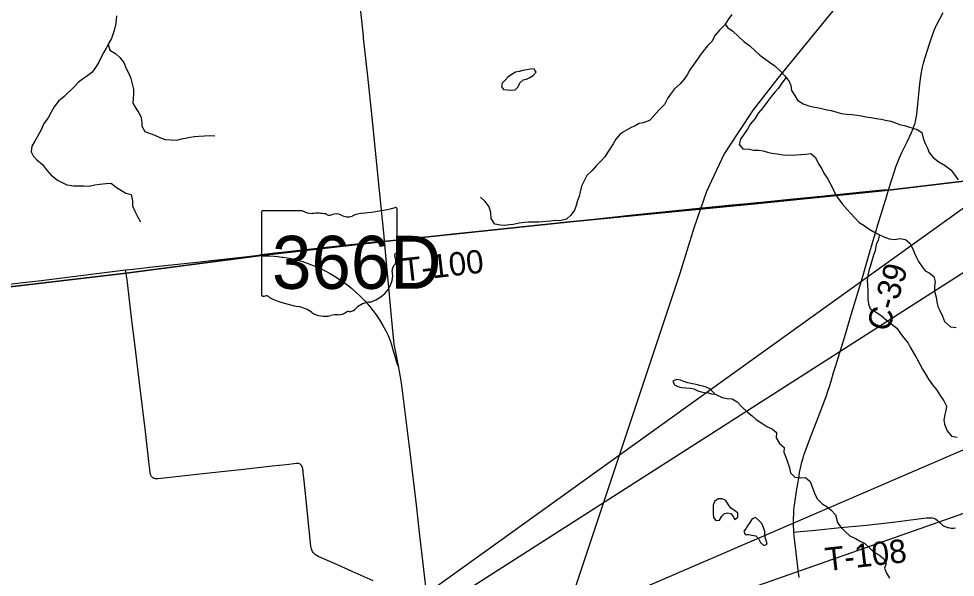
# Model space of a CAD drawing. Extents: x 0 to 34, y -5.4 to 22.
# Drawn here: x 5.117 to 7.394, y 18.075 to 19.432 of the extents above; entities that cross this region are included whole.
import ezdxf

# ---------------------------------------------------------------- set-up
doc = ezdxf.new("R2010")
doc.units = 0
for name, color, linetype in [('GM_X_County_Road', 7, 'Continuous'), ('GM_X_County_Road_Text', 7, 'Continuous'), ('GM_X_Minor_Lake', 7, 'Continuous'), ('GM_X_Minor_River', 7, 'Continuous'), ('GM_X_Rail_Line', 7, 'Continuous'), ('GM_X_State_Location', 7, 'Continuous'), ('GM_X_State_Route', 7, 'Continuous'), ('GM_X_State_Shield', 7, 'Continuous'), ('GM_X_Township_Road', 7, 'Continuous'), ('GM_X_Township_Road_Text', 7, 'Continuous'), ('SH_Data', 7, 'Continuous')]:
    doc.layers.add(name, color=color, linetype=linetype)

msp = doc.modelspace()

# ---------------------------------------------------------------- linework, layer by layer
at = {"layer": 'GM_X_County_Road'}
for points in [[(7.231, 19.0161), (7.2456, 19.0619), (7.249, 19.0719), (7.2529, 19.0817), (7.2574, 19.092), (7.264, 19.1068), (7.2768, 19.1331), (7.2875, 19.1555), (7.2915, 19.1651), (7.294, 19.1721), (7.296, 19.1785), (7.2972, 19.1834), (7.2986, 19.191), (7.2998, 19.1992), (7.3076, 19.274), (7.3107, 19.2969), (7.3124, 19.3059), (7.3142, 19.3146), (7.3165, 19.3238), (7.3179, 19.3294), (7.3196, 19.3351), (7.3315, 19.3731), (7.3408, 19.3995), (7.3434, 19.4059), (7.3457, 19.4111), (7.3483, 19.4166), (7.3639, 19.4471)], [(7.0144, 18.0746), (7.012, 18.0925), (7.0077, 18.1276), (7.0037, 18.1622), (7.0028, 18.1691), (7.0022, 18.175), (7.0014, 18.1844), (7.0008, 18.1919), (7.0005, 18.1991), (7.0002, 18.2066), (7.0002, 18.214), (7.0005, 18.2204), (7.0007, 18.2261), (7.0008, 18.2314), (7.0013, 18.2388), (7.0018, 18.2449), (7.0026, 18.2505), (7.0076, 18.2842), (7.0092, 18.2937), (7.0105, 18.302), (7.0121, 18.3118), (7.0137, 18.3204), (7.0152, 18.3294), (7.0174, 18.3399), (7.019, 18.3474), (7.0206, 18.3544), (7.0219, 18.3593), (7.0234, 18.3652), (7.0253, 18.3712), (7.0276, 18.3781), (7.03, 18.3848), (7.0332, 18.3932), (7.0449, 18.4233), (7.0605, 18.4633), (7.0775, 18.508), (7.0806, 18.5168), (7.0841, 18.5268), (7.0885, 18.5411), (7.0909, 18.5488), (7.0986, 18.5745), (7.103, 18.5892), (7.1118, 18.6184), (7.1247, 18.6599), (7.1396, 18.7099), (7.1679, 18.8032), (7.1861, 18.8659), (7.2081, 18.9393), (7.2246, 18.9932), (7.231, 19.0161)]]:
    msp.add_lwpolyline(points, dxfattribs=at)
at = {"layer": 'GM_X_Minor_Lake'}
for points in [[(6.3718, 19.3068), (6.3699, 19.3104), (6.36, 19.309), (6.3516, 19.3076), (6.3425, 19.3058), (6.3334, 19.3033), (6.3243, 19.3019), (6.3159, 19.2975), (6.3059, 19.2901)], [(6.3059, 19.2901), (6.299, 19.283), (6.292, 19.2751), (6.2904, 19.2664), (6.2956, 19.2599), (6.3051, 19.2593), (6.3145, 19.2584), (6.3236, 19.2591), (6.3306, 19.2662), (6.3349, 19.276), (6.3429, 19.2834), (6.3509, 19.2852), (6.3593, 19.2889), (6.3677, 19.2941), (6.3743, 19.3023), (6.3718, 19.3068)], [(6.8096, 18.52), (6.7972, 18.5327), (6.7882, 18.5371), (6.7799, 18.5391), (6.7724, 18.5407), (6.7637, 18.5431), (6.7546, 18.5448), (6.7433, 18.5472), (6.7339, 18.5504), (6.7256, 18.554), (6.7161, 18.5553), (6.7073, 18.5516), (6.7096, 18.5458)], [(6.7096, 18.5458), (6.711, 18.5424), (6.7189, 18.5385), (6.7283, 18.5361), (6.7382, 18.5352), (6.7488, 18.5346), (6.7582, 18.5326), (6.7676, 18.5275), (6.7755, 18.5251), (6.7842, 18.5242), (6.7925, 18.5229), (6.8009, 18.5209), (6.8096, 18.52)], [(6.8628, 18.219), (6.8653, 18.2207), (6.8651, 18.231), (6.8561, 18.2376), (6.8482, 18.243), (6.8419, 18.2511), (6.8356, 18.2611), (6.8265, 18.2654), (6.8171, 18.2659), (6.8086, 18.2588), (6.8047, 18.2498), (6.8046, 18.2424), (6.8049, 18.2369)], [(6.8049, 18.2369), (6.8048, 18.2289), (6.8054, 18.2201), (6.8113, 18.2125), (6.8205, 18.2135), (6.8259, 18.2232), (6.8324, 18.2296), (6.8404, 18.2318), (6.848, 18.2301), (6.8539, 18.2228), (6.8576, 18.2152), (6.8628, 18.219)], [(6.9343, 18.1544), (6.9363, 18.1551), (6.9341, 18.1639), (6.9312, 18.1719), (6.9302, 18.1802), (6.9303, 18.1863), (6.927, 18.1962), (6.9234, 18.2054), (6.9152, 18.2135), (6.9081, 18.2205), (6.9001, 18.2168), (6.8939, 18.2081), (6.8881, 18.2003), (6.8842, 18.1923)], [(6.8842, 18.1923), (6.8799, 18.1867), (6.8825, 18.1791), (6.8908, 18.179), (6.8987, 18.1773), (6.9085, 18.1753), (6.9156, 18.1672), (6.9197, 18.1595), (6.9279, 18.1522), (6.9343, 18.1544)]]:
    msp.add_lwpolyline(points, dxfattribs=at)
at = {"layer": 'GM_X_Minor_River'}
for points in [[(5.354, 19.439), (5.3535, 19.4292), (5.3517, 19.4167), (5.3489, 19.4034), (5.3418, 19.3838), (5.3344, 19.3702), (5.3289, 19.3601), (5.3238, 19.3503), (5.3172, 19.3382), (5.3106, 19.3247), (5.302, 19.3111), (5.2947, 19.301), (5.2816, 19.2917), (5.2713, 19.2854), (5.2609, 19.2769), (5.2517, 19.2664), (5.2275, 19.2428), (5.2136, 19.2313), (5.2028, 19.2182), (5.1954, 19.2046), (5.1884, 19.1911), (5.1776, 19.1772), (5.1709, 19.1617), (5.1631, 19.1474), (5.1561, 19.1346), (5.1487, 19.1222), (5.147, 19.1086), (5.1521, 19.0986), (5.1607, 19.089), (5.1742, 19.0774), (5.1842, 19.0651), (5.1957, 19.0516), (5.2107, 19.04), (5.2224, 19.0338), (5.2337, 19.0287), (5.2503, 19.0261), (5.2609, 19.0256), (5.2749, 19.0257), (5.2882, 19.0255), (5.3015, 19.0287), (5.314, 19.0301), (5.3296, 19.0317), (5.3414, 19.0327), (5.3545, 19.0222), (5.3661, 19.0145), (5.3774, 19.0082), (5.3898, 19.005), (5.393, 18.9894), (5.3932, 18.9772), (5.3987, 18.9642), (5.4053, 18.9516), (5.4123, 18.9382)], [(6.8501, 19.4423), (6.8416, 19.4302), (6.8331, 19.4171), (6.8204, 19.4044), (6.8096, 19.392), (6.8014, 19.3766), (6.7914, 19.3661), (6.7805, 19.353), (6.772, 19.3406), (6.7631, 19.3282), (6.7484, 19.3079), (6.7414, 19.2959), (6.7348, 19.2854), (6.7244, 19.2738), (6.7113, 19.2618), (6.7016, 19.2487), (6.6943, 19.2378)], [(6.8341, 19.4188), (6.8398, 19.4105), (6.8525, 19.4016), (6.8667, 19.3885), (6.8806, 19.3761), (6.894, 19.3657), (6.9067, 19.3541), (6.9187, 19.3436), (6.9299, 19.3351), (6.9419, 19.3266), (6.9551, 19.3176), (6.9685, 19.3041), (6.9801, 19.2926), (6.9901, 19.2795), (6.9934, 19.27), (6.9958, 19.2574), (7.004, 19.244), (7.0103, 19.234), (7.0241, 19.2255), (7.0373, 19.2199), (7.0471, 19.2179), (7.0615, 19.2154), (7.0713, 19.213), (7.0819, 19.2105), (7.0917, 19.2089), (7.1053, 19.2048), (7.117, 19.2016), (7.1291, 19.1999), (7.1424, 19.199), (7.1552, 19.198), (7.1658, 19.1963), (7.1764, 19.1939), (7.1892, 19.1922), (7.2013, 19.1897), (7.2138, 19.1876), (7.224, 19.1855), (7.2372, 19.1831), (7.2481, 19.1787), (7.2583, 19.1748), (7.27, 19.1723), (7.2798, 19.1691), (7.2908, 19.1659), (7.3006, 19.1627), (7.3122, 19.1553), (7.3158, 19.1416), (7.3205, 19.1286), (7.326, 19.1175), (7.33, 19.1068), (7.3401, 19.0945), (7.3539, 19.0844), (7.369, 19.0751), (7.3824, 19.065), (7.3906, 19.0546), (7.401, 19.0404)], [(5.3338, 19.3692), (5.3383, 19.3558), (5.3518, 19.3472), (5.3623, 19.3379), (5.372, 19.3252), (5.3778, 19.3111), (5.3844, 19.2985), (5.3888, 19.287), (5.3924, 19.2737), (5.3956, 19.2607), (5.3954, 19.2501), (5.3949, 19.2376), (5.3943, 19.2266), (5.3995, 19.217), (5.4088, 19.2036), (5.4139, 19.194), (5.4156, 19.1803), (5.4158, 19.1705), (5.4236, 19.1582), (5.4364, 19.1527), (5.4473, 19.1487), (5.4594, 19.1432), (5.4726, 19.1385), (5.4866, 19.1379), (5.5013, 19.1369), (5.5124, 19.1401), (5.5219, 19.1419), (5.5337, 19.144), (5.5439, 19.1461), (5.5542, 19.1463), (5.5682, 19.1472), (5.5826, 19.1482), (5.5936, 19.1472)], [(6.9826, 19.2893), (6.9734, 19.2775), (6.9637, 19.2632), (6.9552, 19.2531), (6.9471, 19.2434), (6.9367, 19.2306), (6.9259, 19.2156), (6.915, 19.2029), (6.9061, 19.189), (6.8957, 19.1766), (6.8883, 19.1634), (6.8809, 19.1533), (6.8713, 19.1394), (6.868, 19.1265), (6.877, 19.1154), (6.8925, 19.1148), (6.9042, 19.1127), (6.9156, 19.1125), (6.9265, 19.1108), (6.9371, 19.1076), (6.9473, 19.1056), (6.9617, 19.1038), (6.9749, 19.101), (6.9908, 19.1003), (7.0056, 19.1012), (7.0181, 19.1022), (7.0299, 19.1031), (7.0428, 19.1041), (7.0536, 19.0944), (7.0613, 19.0791), (7.0691, 19.0669), (7.0742, 19.0565), (7.0831, 19.0435), (7.089, 19.0328), (7.0942, 19.0224), (7.1004, 19.0083), (7.1071, 18.9979), (7.1182, 18.9822), (7.1305, 18.9687), (7.1398, 18.9583), (7.1491, 18.9483), (7.1603, 18.9371), (7.1723, 18.9293), (7.184, 18.9208), (7.1937, 18.9146), (7.2061, 18.9087), (7.2197, 18.9024), (7.2332, 18.8973), (7.2469, 18.8959), (7.259, 18.8976), (7.2726, 18.8959), (7.2831, 18.887), (7.2897, 18.8748), (7.2945, 18.8625), (7.2996, 18.8514), (7.3044, 18.8419), (7.3133, 18.8288), (7.32, 18.8192), (7.3305, 18.8149), (7.3414, 18.8056), (7.345, 18.7927), (7.3429, 18.7817), (7.3431, 18.7699), (7.3474, 18.7558), (7.3488, 18.7444), (7.3512, 18.7326), (7.3564, 18.723), (7.3626, 18.7092), (7.3674, 18.6963), (7.3823, 18.6835), (7.3956, 18.6814)], [(6.6943, 19.2378), (6.6865, 19.2239), (6.673, 19.21), (6.6607, 19.1962), (6.6499, 19.1849), (6.6346, 19.1787), (6.6252, 19.1774), (6.6152, 19.1718), (6.6057, 19.1678), (6.5889, 19.1578), (6.5789, 19.1515), (6.5685, 19.1391), (6.5615, 19.1279), (6.5549, 19.1166), (6.5483, 19.1068), (6.5413, 19.0967), (6.5317, 19.0862), (6.5217, 19.0757), (6.5109, 19.0633), (6.4978, 19.051), (6.4912, 19.0382), (6.4849, 19.0254), (6.4817, 19.011), (6.4788, 19.0004), (6.4753, 18.9899), (6.4721, 18.9785), (6.4681, 18.9668), (6.4588, 18.9544), (6.4481, 18.9447), (6.4325, 18.9412), (6.4211, 18.9413), (6.4105, 18.9404), (6.3995, 18.9394), (6.39, 18.9388), (6.3801, 18.9378), (6.3672, 18.938), (6.3559, 18.9374), (6.346, 18.9368), (6.3335, 18.9351), (6.319, 18.9323), (6.3095, 18.9309), (6.2985, 18.9299), (6.2879, 18.9305), (6.2739, 18.9326), (6.2654, 18.9468), (6.2645, 18.9612), (6.2602, 18.9749), (6.2509, 18.9876), (6.2397, 18.9984)], [(7.2096, 18.9071), (7.2063, 18.8939), (7.2016, 18.8833), (7.1987, 18.8682), (7.1951, 18.8576), (7.1911, 18.8436), (7.1872, 18.8327), (7.1844, 18.8225), (7.1807, 18.8081), (7.1794, 18.796), (7.18, 18.7857), (7.1806, 18.7728), (7.1812, 18.761), (7.1814, 18.7504), (7.1823, 18.7394), (7.1863, 18.7268), (7.1995, 18.7194), (7.2134, 18.7112), (7.2264, 18.6992), (7.2519, 18.6798), (7.2604, 18.6672), (7.2686, 18.6568), (7.279, 18.6437), (7.2838, 18.6342), (7.2941, 18.6158), (7.3004, 18.6062), (7.3071, 18.5928), (7.3141, 18.5809), (7.3204, 18.5702), (7.3285, 18.5564), (7.3381, 18.5426), (7.3485, 18.5295), (7.3567, 18.5169), (7.366, 18.5038), (7.3722, 18.4904), (7.3705, 18.4798), (7.3681, 18.47), (7.366, 18.4567), (7.367, 18.4465), (7.3736, 18.4308), (7.3844, 18.4181), (7.3983, 18.4152)], [(6.8096, 18.52), (6.8268, 18.5118), (6.8392, 18.5093), (6.8513, 18.5084), (6.8637, 18.5013), (6.8752, 18.4879), (6.8886, 18.4762), (6.8998, 18.4673), (6.9095, 18.4584), (6.9234, 18.4491), (6.9357, 18.4409), (6.9489, 18.435), (6.9586, 18.4269), (6.9583, 18.414), (6.9664, 18.4002), (6.9772, 18.3902), (6.9771, 18.3791), (6.9814, 18.3666), (6.9865, 18.3528), (6.9908, 18.3406), (6.9933, 18.3288), (7.0033, 18.3184), (7.0176, 18.3166), (7.0298, 18.3172), (7.0406, 18.3079), (7.0442, 18.2983), (7.0482, 18.288), (7.0522, 18.2766), (7.0588, 18.2643), (7.0703, 18.2531), (7.0801, 18.2473), (7.092, 18.238), (7.1021, 18.2268), (7.107, 18.2077), (7.1148, 18.1977), (7.1263, 18.185), (7.1375, 18.1757), (7.1507, 18.1691), (7.1604, 18.1636), (7.1735, 18.1569), (7.1844, 18.1469), (7.1952, 18.1361), (7.2068, 18.1302), (7.2187, 18.1205), (7.2253, 18.1086), (7.2217, 18.0969), (7.2265, 18.0851), (7.2335, 18.0724)]]:
    msp.add_lwpolyline(points, dxfattribs=at)
at = {"layer": 'GM_X_Rail_Line'}
msp.add_lwpolyline([(8.9, 19.2127), (8.9, 20.9), (3.5133, 20.9), (3.5122, 20.8763), (3.4778, 20.1697), (3.46, 19.8188), (3.4303, 19.2337), (3.4301, 19.2311), (3.4297, 19.2264), (3.3865, 18.7781), (3.3669, 18.5872), (3.5131, 18.6037), (4.7505, 18.7432), (5.0255, 18.7742), (5.096, 18.7806), (5.378, 18.814), (5.7313, 18.8595), (5.7334, 18.8597), (6.0045, 18.8908), (6.4496, 18.9373), (6.6792, 18.9603), (6.9054, 18.9823), (7.2315, 19.0156), (8.5201, 19.1691)], close=True, dxfattribs=at)
for points in [[(8.2982, 20.9), (7.9149, 20.4347), (7.2657, 19.6601), (6.962, 19.2874), (6.9019, 19.2104), (6.8655, 19.1557), (6.8321, 19.1035), (6.789, 19.0121), (6.7581, 18.9233), (6.7239, 18.8129), (6.4727, 18.0601), (6.244, 17.3648), (6.1298, 17.0307)], [(8.9, 15.5944), (8.9, 19.2127), (8.5201, 19.1691), (7.2315, 19.0156), (6.9054, 18.9823), (6.6792, 18.9603), (6.4496, 18.9373), (6.0045, 18.8908), (5.7334, 18.8597), (5.7313, 18.8595), (5.378, 18.814), (5.096, 18.7806), (5.0255, 18.7742), (4.7505, 18.7432), (3.5131, 18.6037), (3.3669, 18.5872), (3.3607, 18.5226), (3.3599, 18.5136), (3.2432, 17.2942), (3.13, 16.1326)]]:
    msp.add_lwpolyline(points, dxfattribs=at)
at = {"layer": 'GM_X_State_Route'}
for points in [[(5.8714, 20.1687), (5.8744, 20.1399), (5.8745, 20.1384), (5.886, 20.0226), (5.8984, 19.9027), (5.9152, 19.7476), (5.9312, 19.6), (5.9491, 19.435), (5.9537, 19.3905), (5.9544, 19.3846)], [(5.9544, 19.3846), (5.9645, 19.2923), (5.9753, 19.1916), (5.9931, 19.0148), (6.0041, 18.9034), (6.0052, 18.8912)], [(6.0052, 18.8912), (5.9892, 18.8895), (5.9464, 18.8849), (5.8785, 18.8774), (5.7635, 18.8648), (5.7463, 18.8629), (5.7004, 18.8576)], [(6.0052, 18.8912), (6.0157, 18.7791), (6.0222, 18.7073), (6.0272, 18.6572), (6.0279, 18.6498), (6.029, 18.6409), (6.0302, 18.6342), (6.0306, 18.6321)], [(4.9909, 18.7831), (4.9947, 18.7825), (5.0069, 18.7811), (5.0191, 18.7803), (5.0304, 18.7803), (5.0463, 18.7815), (5.0672, 18.7836), (5.1201, 18.7901), (5.1708, 18.7963), (5.319, 18.8147), (5.3771, 18.8215), (5.3952, 18.8236), (5.4492, 18.8298), (5.5498, 18.8408), (5.5998, 18.8465), (5.6652, 18.8537), (5.7004, 18.8576)], [(5.7004, 18.8576), (5.7048, 18.8568), (5.7092, 18.8562), (5.7128, 18.856), (5.7201, 18.8559), (5.7275, 18.8556), (5.7379, 18.8551), (5.7463, 18.8543), (5.7518, 18.8536), (5.7561, 18.853)], [(5.7561, 18.853), (5.7592, 18.8526), (5.7745, 18.8498), (5.7897, 18.8465), (5.804, 18.8425), (5.8182, 18.8379), (5.8328, 18.8327), (5.8448, 18.8277), (5.8583, 18.8213), (5.8741, 18.8127), (5.8885, 18.8041), (5.9015, 18.7955), (5.914, 18.7864), (5.9257, 18.7771), (5.9374, 18.7669), (5.9477, 18.757), (5.9589, 18.7454), (5.9691, 18.7337), (5.9776, 18.723), (5.9853, 18.7125), (5.9935, 18.7), (6.0016, 18.6868), (6.0092, 18.6734), (6.0145, 18.6624), (6.0193, 18.6505), (6.0236, 18.6371), (6.026, 18.6283), (6.0365, 18.5923), (6.037, 18.5912), (6.038, 18.5899), (6.0388, 18.589)], [(6.0306, 18.6321), (6.0317, 18.626), (6.0388, 18.589)], [(6.0388, 18.589), (6.0431, 18.5659), (6.0463, 18.5467), (6.049, 18.5279), (6.0672, 18.3786), (6.0826, 18.2509), (6.0912, 18.1762), (6.0987, 18.1145), (6.1083, 18.0305), (6.1106, 18.0074), (6.1167, 17.9439), (6.1271, 17.8601), (6.1412, 17.7428), (6.151, 17.6639), (6.1545, 17.6306)]]:
    msp.add_lwpolyline(points, dxfattribs=at)
at = {"layer": 'GM_X_State_Shield'}
for p, q in [((6.0364, 18.8655), (6.0364, 18.9701)), ((5.7068, 18.9617), (5.7068, 18.7616)), ((5.8066, 18.9652), (5.71, 18.9652)), ((6.0363, 18.8655), (6.0364, 18.8655))]:
    msp.add_line(p, q, dxfattribs=at)
for centre, major_axis, start_param, end_param in [((5.919, 19.238), (0.3495, 0), 4.814394, 5.042369), ((6.0327, 18.9706), (0.00367, 0), 6.141152, 7.989035), ((5.7106, 18.9622), (0.00382, 0), 1.712693, 3.28349), ((5.8295, 18.9884), (0.037, 0), 4.042523, 4.731795), ((5.8418, 18.8528), (0.133, 0), 1.404758, 1.657858), ((5.872, 18.9632), (0.0107, 0), 3.836095, 5.185415), ((5.8877, 18.9401), (0.0222, 0), 0.950623, 2.079405), ((5.9164, 18.9718), (0.0267, 0), 4.081561, 5.145723), ((5.9636, 18.9041), (0.0703, 0), 1.699011, 2.107814), ((6.0355, 18.8578), (0.00568, 0), 1.883978, 3.671073), ((5.9994, 18.8445), (0.0341, 0), 5.934695, 6.695948), ((6.0325, 18.865), (0.00393, 0), 5.05454, 6.418171), ((6.0495, 18.8216), (0.0248, 0), 2.387724, 3.262537), ((5.9386, 18.8083), (0.0874, 0), 5.101752, 6.440018), ((5.7106, 18.7612), (0.00385, 0), 3.00124, 4.508301), ((5.7112, 18.7817), (0.0294, 0), 4.665946, 4.897461), ((5.7172, 18.7501), (0.0106, 0), 0.519207, 1.627899), ((5.851, 18.9299), (0.2524, 0), 4.195997, 4.488961), ((5.9754, 18.7054), (0.0479, 0), 1.647645, 2.488434), ((5.7758, 18.6717), (0.079, 0), 0.823519, 1.323587), ((5.8612, 18.7491), (0.0501, 0), 4.026481, 4.996735), ((5.8938, 18.7341), (0.0267, 0), 4.691044, 5.507374), ((5.918, 18.7147), (0.00752, 0), 1.147584, 2.315152), ((5.9148, 18.7422), (0.0282, 0), 4.937069, 5.64225), ((5.8901, 18.6799), (0.0412, 0), 1.495662, 1.94098)]:
    msp.add_ellipse(centre, major_axis=major_axis, ratio=0.8, start_param=start_param, end_param=end_param, dxfattribs=at)
at = {"layer": 'GM_X_Township_Road'}
for points in [[(6.0052, 18.8912), (6.0099, 18.8918), (6.0796, 18.8997), (6.1514, 18.9071), (6.1711, 18.909), (6.2274, 18.915), (6.2614, 18.9186), (6.3059, 18.9234), (6.3424, 18.9271), (6.4234, 18.9352), (6.4629, 18.9393), (6.5593, 18.9499), (6.61, 18.9553), (6.6663, 18.9609), (6.7306, 18.9674), (6.7701, 18.9716), (6.8103, 18.9755), (6.8505, 18.9795), (6.8877, 18.9831), (6.9532, 18.9898), (6.9915, 18.9937), (7.0169, 18.9962), (7.0756, 19.002), (7.1597, 19.0105), (7.2086, 19.0151), (7.2173, 19.0159), (7.2224, 19.0163), (7.2271, 19.0163), (7.231, 19.0161)], [(5.9781, 18.0662), (5.9271, 18.089), (5.884, 18.1082), (5.8504, 18.123), (5.846, 18.1249), (5.8425, 18.1269), (5.8405, 18.1282), (5.8382, 18.1296), (5.8349, 18.1326), (5.8323, 18.1355), (5.831, 18.1374), (5.8301, 18.1394), (5.8291, 18.1419), (5.8284, 18.1442), (5.8276, 18.1474), (5.8271, 18.1504), (5.8231, 18.1901), (5.8152, 18.2623), (5.8103, 18.3093), (5.8084, 18.3291), (5.8078, 18.3334), (5.8075, 18.336), (5.8071, 18.3386), (5.8066, 18.3412), (5.8058, 18.3435), (5.8049, 18.3453), (5.8037, 18.3471), (5.8025, 18.3485), (5.801, 18.3495), (5.7991, 18.3505), (5.7969, 18.351), (5.7948, 18.3512), (5.792, 18.3511), (5.7667, 18.3484), (5.7328, 18.3446), (5.6568, 18.3362), (5.6099, 18.3313), (5.5426, 18.3239), (5.4777, 18.3168), (5.4548, 18.3141), (5.4526, 18.314), (5.451, 18.3141), (5.4489, 18.3143), (5.4471, 18.3146), (5.445, 18.3153), (5.4431, 18.3163), (5.4415, 18.3175), (5.4401, 18.3189), (5.4389, 18.3207), (5.4381, 18.3222), (5.4375, 18.3239), (5.4369, 18.3256), (5.4365, 18.3278), (5.4361, 18.3302), (5.4354, 18.337), (5.4331, 18.3558), (5.4245, 18.429), (5.4102, 18.5475), (5.3988, 18.6424), (5.3919, 18.6985), (5.3862, 18.7479), (5.3811, 18.791), (5.3774, 18.8188), (5.3771, 18.8215)], [(7.0014, 18.1844), (7.0072, 18.185), (7.0536, 18.1897), (7.1148, 18.1958), (7.1779, 18.2019), (7.2488, 18.2099), (7.2852, 18.2142), (7.3173, 18.2185), (7.3239, 18.2192), (7.3277, 18.2195), (7.3311, 18.2197), (7.3345, 18.2197), (7.3378, 18.2193), (7.3409, 18.2186), (7.3433, 18.2177), (7.3461, 18.2162), (7.3496, 18.2135), (7.3532, 18.2104), (7.3568, 18.2071), (7.36, 18.204), (7.3628, 18.2018), (7.3652, 18.2001), (7.3682, 18.1984), (7.3714, 18.1971), (7.3744, 18.1961), (7.3769, 18.1955), (7.3806, 18.1947), (7.3836, 18.1945), (7.3868, 18.1944), (7.3902, 18.1946), (7.3945, 18.1949)]]:
    msp.add_lwpolyline(points, dxfattribs=at)
at = {"layer": 'SH_Data'}
for points in [[(9.2327, 20.2782), (5.4298, 17.5482), (9.2327, 19.9788)], [(9.2327, 19.1682), (5.4895, 17.5552), (9.2327, 18.8687)]]:
    msp.add_lwpolyline(points, close=True, dxfattribs=at)

# ---------------------------------------------------------------- texts
at = {"layer": 'GM_X_County_Road_Text'}
msp.add_text('C-39', height=0.05682, rotation=73.3061, dxfattribs=at).set_placement((7.2316, 18.6691))
at = {"layer": 'GM_X_State_Location'}
msp.add_text('366D', height=0.000189, rotation=0, dxfattribs=at).set_placement((5.7877, 18.8401))
for s in ['s', 'r']:
    msp.add_text(s, height=0.000189, dxfattribs=at).set_placement((5.8679, 18.8484))
at = {"layer": 'GM_X_State_Shield'}
msp.add_text('366D', height=0.12879, dxfattribs=at).set_placement((5.7325, 18.7757))
at = {"layer": 'GM_X_Township_Road_Text'}
for s, p in [('T-100', (6.0522, 18.793)), ('T-108', (7.0805, 18.0897))]:
    msp.add_text(s, height=0.05682, rotation=6.4955, dxfattribs=at).set_placement(p)

doc.saveas('drawing.dxf')
